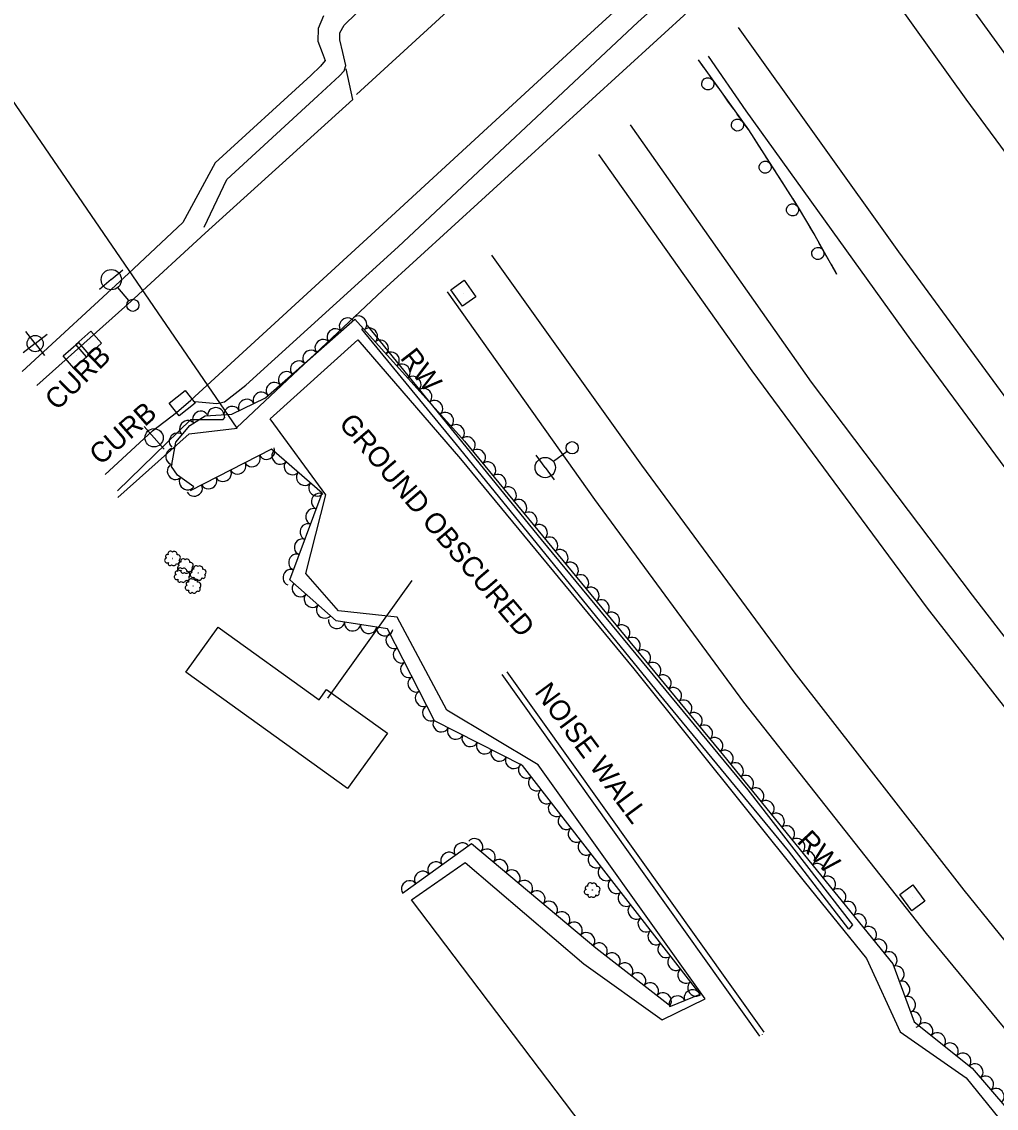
# Model space of a CAD drawing. Extents: x 1722896 to 1754269, y 648279 to 666297.
# Drawn here: x 1731974.7 to 1732214.8, y 650380.2 to 650647.8 of the extents above; entities that cross this region are included whole.
import ezdxf

# ---------------------------------------------------------------- set-up
doc = ezdxf.new("R2010")
doc.units = 0
for name, color, linetype in [('DESIGN - CENTERLINE - Proposed', 7, 'Continuous'), ('DESIGN - CENTERLINE - Proposed Text', 7, 'Continuous'), ('DESIGN - CONTOURS - Intermediate with optional Text', 7, 'Continuous'), ('DESIGN - SCRATCH - User 1', 7, 'Continuous'), ('SURVEY - CENTERLINE - Preliminary', 7, 'Continuous'), ('SURVEY - CENTERLINE - Preliminary Text', 7, 'Continuous'), ('SURVEY - DRAINAGE - Natural Features', 7, 'Continuous'), ('SURVEY - DTM - Breaklines', 7, 'Continuous'), ('SURVEY - VEGETATION - Features with Text', 7, 'Continuous')]:
    doc.layers.add(name, color=color, linetype=linetype)

msp = doc.modelspace()

# ---------------------------------------------------------------- linework, layer by layer
at = {"layer": 'DESIGN - CENTERLINE - Proposed'}
for points in [[(1732027.76, 650547.7), (1731948.68, 650663.25), (1732016.79, 650725.98), (1732087.03, 650790.21), (1732126.29, 650827.23)], [(1732204.27, 650710.7), (1732204.36, 650710.57), (1732139.74, 650651.07), (1732063.58, 650581.67), (1732027.75, 650547.92)]]:
    msp.add_lwpolyline(points, dxfattribs=at)
at = {"layer": 'DESIGN - CENTERLINE - Proposed Text'}
for points in [[(1731998.43, 650530.69), (1732015.98, 650546.35), (1732027.76, 650547.7)], [(1731998.43, 650530.69), (1732015.98, 650546.35), (1732027.76, 650547.7)], [(1732050.11, 650481.21), (1732070.87, 650510.2)], [(1732050.11, 650481.21), (1732070.87, 650510.2)]]:
    msp.add_lwpolyline(points, dxfattribs=at)
msp.add_lwpolyline([(1732015.16, 650487.66), (1732023.12, 650498.71), (1732047.97, 650480.81), (1732049.83, 650483.39), (1732064.8, 650472.61), (1732054.98, 650458.98)], close=True, dxfattribs=at)
at = {"layer": 'DESIGN - CONTOURS - Intermediate with optional Text'}
for q in [(1731975.77, 650571.55), (1731981.02, 650570.85), (1731975.07, 650566.29), (1731980.32, 650565.59)]:
    msp.add_line((1731978.04, 650568.57), q, dxfattribs=at)
msp.add_circle((1731978.04, 650568.57), 2, dxfattribs=at)
at = {"layer": 'DESIGN - SCRATCH - User 1'}
for points in [[(1732141.32, 650638.47), (1732153.75, 650621.19), (1732166.02, 650602.07), (1732170.07, 650595.18), (1732175.47, 650585.65)], [(1732141.32, 650638.47), (1732142.69, 650636.56)], [(1732143.62, 650635.26), (1732146.31, 650631.53)], [(1732147.24, 650630.23), (1732148.62, 650628.32)], [(1732148.62, 650628.32), (1732149.99, 650626.41)], [(1732150.92, 650625.11), (1732153.61, 650621.38)], [(1732154.48, 650620.04), (1732155.75, 650618.06)], [(1732155.75, 650618.06), (1732157.02, 650616.08)], [(1732157.89, 650614.74), (1732160.37, 650610.87)], [(1732161.24, 650609.52), (1732162.51, 650607.54)], [(1732162.51, 650607.54), (1732163.78, 650605.57)], [(1732164.64, 650604.22), (1732166.02, 650602.07), (1732167.05, 650600.31)], [(1732167.86, 650598.93), (1732169.05, 650596.9)], [(1732169.05, 650596.9), (1732170.07, 650595.18), (1732170.24, 650594.87)], [(1732171.03, 650593.48), (1732173.3, 650589.48)], [(1732174.09, 650588.09), (1732175.25, 650586.04)], [(1732175.25, 650586.04), (1732175.47, 650585.65)], [(1732059.81, 650573.02), (1732102.66, 650520.33), (1732153.61, 650458.61), (1732179.34, 650425.38), (1732178.44, 650424.33), (1732163.6, 650443.58), (1732131.75, 650482.28), (1732081.81, 650543.7), (1732058.48, 650572.12), (1732058.68, 650572.25)], [(1732059.56, 650572.85), (1732059.81, 650573.02)], [(1732156.53, 650397.99), (1732124.59, 650442.81), (1732093.08, 650487.08)], [(1732094.24, 650487.73), (1732157.49, 650398.95)], [(1732157.16, 650398.34), (1732157.11, 650398.29)]]:
    msp.add_lwpolyline(points, dxfattribs=at)
for centre, start, end in [((1732143.74, 650632.54), 148.9899, 148.9801), ((1732151.04, 650622.39), 148.9899, 148.9801), ((1732157.86, 650612.01), 145.9594, 145.9496), ((1732164.61, 650601.49), 145.9594, 145.9496), ((1732170.85, 650590.76), 142.8362, 142.8264)]:
    msp.add_arc(centre, 1.5, start, end, dxfattribs=at)
at = {"layer": 'SURVEY - CENTERLINE - Preliminary'}
msp.add_lwpolyline([(1732127.41, 650356.71), (1732070.78, 650431.51), (1732083.93, 650440.75), (1732113.2, 650415.77), (1732132.47, 650401.96), (1732143.05, 650407.14), (1732101.92, 650464.8), (1732079.44, 650478.24), (1732067.24, 650501.17), (1732052.76, 650502.71), (1732044.68, 650511.92), (1732049.65, 650531.34), (1732035.93, 650550.04), (1732057.56, 650569.48), (1732082.82, 650540.17), (1732125.54, 650488.48), (1732167.48, 650436.04), (1732182.81, 650417.11), (1732191.08, 650399.01), (1732207.4, 650387.66), (1732234.27, 650354.45)], dxfattribs=at)
at = {"layer": 'SURVEY - CENTERLINE - Preliminary Text'}
for points in [[(1732017.39, 650554.27), (1732022.82, 650553.77), (1732024.65, 650554.19), (1732029.89, 650558.35), (1732067.45, 650592.39), (1732126.48, 650647.73), (1732181.2, 650696.92), (1732205.98, 650719.16), (1732222.53, 650735.2), (1732218.17, 650739.56), (1732238.67, 650758.11), (1732258.13, 650774.82)], [(1732019.7, 650597.23), (1732025.25, 650609), (1732047.69, 650629.57), (1732053, 650634.51), (1732054.14, 650635.79), (1732054.58, 650637.05), (1732053.81, 650640.28), (1732053.05, 650643.35), (1732053.09, 650645.15), (1732054.13, 650647), (1732057.12, 650649.84), (1732093.89, 650683.21), (1732153.25, 650737.93), (1732155.46, 650738.31), (1732157.6, 650737.83), (1732164.05, 650736.16), (1732178.68, 650749.33)], [(1732170.07, 650733.54), (1732117.51, 650685.24), (1732057.17, 650629.93)], [(1732207.17, 650729.36), (1732164.78, 650690.72), (1732112.04, 650642.46), (1732063.76, 650598.07), (1732016.4, 650554.62)], [(1732656.46, 650208.97), (1732630.79, 650210.68), (1732597.44, 650234.52), (1732563.92, 650259.85), (1732539.06, 650279.24), (1732510.61, 650303.52), (1732476.55, 650333.08), (1732451.2, 650357.5), (1732426.04, 650382.28), (1732392, 650419.06), (1732364.07, 650450.35), (1732335.07, 650484.5), (1732308.14, 650518.04), (1732281.58, 650551.51), (1732254.43, 650588.37), (1732226.27, 650627.09), (1732196.58, 650668.11), (1732187.42, 650681.36)], [(1732177.23, 650670.78), (1732207.28, 650628.76), (1732240.27, 650584.01), (1732277.17, 650534.26), (1732308.17, 650494.8), (1732347.59, 650447.31), (1732385.2, 650405.27), (1732423.32, 650365.2), (1732455.21, 650333.82), (1732493.46, 650299.04), (1732525.54, 650271.93), (1732567.3, 650239.43), (1732600.18, 650214.95), (1732636.27, 650190.54), (1732676.54, 650164.63), (1732716.69, 650140.93), (1732760.83, 650117.07), (1732799.05, 650097.55)], [(1732049.03, 650649.33), (1732047.73, 650646.22), (1732047.69, 650643.08), (1732048.73, 650640.25), (1732049.45, 650638.28), (1732048.33, 650636.86), (1732045.97, 650634.61), (1732022.36, 650613.05), (1732014.38, 650598.43), (1732001.02, 650585.83), (1731974.85, 650561.69)], [(1732778.62, 650068.08), (1732748.36, 650083.69), (1732696.91, 650111.79), (1732659.43, 650133.9), (1732618.71, 650159.74), (1732569.4, 650193.82), (1732523.94, 650227.88), (1732487.08, 650258.27), (1732439.71, 650299.95), (1732393.89, 650344.9), (1732345.63, 650396.27), (1732315.87, 650430.1), (1732281.7, 650470.92), (1732248.95, 650512.82), (1732219.45, 650552.09), (1732190.79, 650591.17), (1732151.27, 650646.44)], [(1732143.79, 650639.34), (1732153.13, 650625.88), (1732193.64, 650569.45), (1732232.08, 650517.33), (1732271.5, 650466.99), (1732311.93, 650418.7), (1732362.13, 650362.86), (1732398.54, 650325.18), (1732431.93, 650292.77), (1732461.34, 650265.94), (1732489.99, 650242.08), (1732529.79, 650210.06), (1732579.85, 650173.43), (1732625.15, 650142.57), (1732670.82, 650114.68), (1732714.02, 650089.97), (1732772.83, 650059.19)], [(1732019.92, 650595.73), (1732056.26, 650628.73), (1732054.68, 650636.23)], [(1732758.57, 650037.66), (1732711.61, 650061.49), (1732673.88, 650082.51), (1732628.45, 650110.48), (1732577.41, 650143.72), (1732530.35, 650177.49), (1732484.46, 650213.66), (1732441.73, 650249.76), (1732398.13, 650290.47), (1732360.12, 650328.45), (1732319.14, 650371.25), (1732281.23, 650415.01), (1732242.63, 650463.01), (1732208.97, 650506.59), (1732169.3, 650559.09), (1732132.45, 650611.35), (1732124.72, 650622.47)], [(1732116.77, 650615.12), (1732154.56, 650561.87), (1732197.78, 650503.43), (1732240.48, 650448.7), (1732279.53, 650400.92), (1732304.66, 650372.14), (1732330.13, 650344.56), (1732363.24, 650310.31), (1732395.54, 650278.52), (1732428.24, 650247.68), (1732459.96, 650219.74), (1732492.98, 650192.82), (1732520.72, 650171.8), (1732555.83, 650146.42), (1732590.52, 650122.88), (1732625.42, 650100.02), (1732661.59, 650078.24), (1732702.96, 650054.7), (1732752.88, 650028.99)], [(1731978.43, 650558.21), (1732002.46, 650579.65), (1732019.92, 650595.73)], [(1732733.54, 649998.91), (1732697.9, 650017.32), (1732664.31, 650035.65), (1732632.41, 650053.89), (1732595.91, 650076.67), (1732547.12, 650109.2), (1732508.27, 650137.06), (1732471.36, 650165.08), (1732438.09, 650192.32), (1732405.65, 650220.47), (1732374.22, 650249.28), (1732344.15, 650278.5), (1732307.7, 650316.31), (1732271.64, 650356.22), (1732236.11, 650397.76), (1732206.87, 650433.94), (1732165.04, 650487.7), (1732127.45, 650538.61), (1732090.56, 650590.36)], [(1732079.49, 650581.32), (1732115.82, 650530.17), (1732152.56, 650480.2), (1732197.55, 650423.24), (1732252.84, 650356.13), (1732285.21, 650320.71), (1732328.53, 650274.62), (1732371.38, 650233.06), (1732418.71, 650190.71), (1732459.87, 650156.35), (1732498.95, 650126.41), (1732536.17, 650100.02), (1732559.49, 650083.88), (1732563.6, 650063.54)], [(1731995.28, 650536.28), (1732006.93, 650547.11), (1732012.84, 650551.61), (1732016.4, 650554.62)], [(1731998.32, 650532.27), (1732016.42, 650549.84), (1732024.31, 650549.83), (1732024.75, 650550.34)]]:
    msp.add_lwpolyline(points, dxfattribs=at)
at = {"layer": 'SURVEY - DRAINAGE - Natural Features'}
for p, q in [((1732083.5, 650580.97), (1732083.5, 650580.97)), ((1731991.22, 650568.49), (1731991.22, 650568.49)), ((1731988.14, 650565.68), (1731988.14, 650565.68)), ((1732014.24, 650553.89), (1732014.24, 650553.89)), ((1732194.13, 650432), (1732194.13, 650432))]:
    msp.add_line(p, q, dxfattribs=at)
for points in [[(1732080.42, 650581.84), (1732083.68, 650584.16), (1732086.58, 650580.09), (1732083.32, 650577.77), (1732080.42, 650581.84)], [(1731991.78, 650571.64), (1731994.41, 650568.63), (1731990.65, 650565.33), (1731988.02, 650568.34), (1731991.78, 650571.64)], [(1731988.7, 650568.83), (1731991.34, 650565.83), (1731987.59, 650562.53), (1731984.95, 650565.53), (1731988.7, 650568.83)], [(1732014.96, 650557.01), (1732017.44, 650553.88), (1732013.52, 650550.77), (1732011.04, 650553.9), (1732014.96, 650557.01)], [(1732191.04, 650432.83), (1732194.26, 650435.2), (1732197.23, 650431.18), (1732194.01, 650428.81), (1732191.04, 650432.83)]]:
    msp.add_lwpolyline(points, dxfattribs=at)
at = {"layer": 'SURVEY - DTM - Breaklines'}
for p, q in [((1731996.79, 650584.31), (1731999.65, 650586.73)), ((1731996.79, 650584.31), (1731993.92, 650581.88)), ((1732001.15, 650579.15), (1731998.4, 650582.4)), ((1732007.33, 650545.36), (1732004.86, 650548.18)), ((1732007.33, 650545.36), (1732009.81, 650542.54)), ((1732103.69, 650538.02), (1732101.47, 650541.04)), ((1732109.12, 650542.02), (1732105.7, 650539.5)), ((1732103.69, 650538.02), (1732105.91, 650535))]:
    msp.add_line(p, q, dxfattribs=at)
for centre, radius in [((1731996.79, 650584.31), 2.5), ((1732002.11, 650578), 1.5), ((1732007.33, 650545.36), 2.25), ((1732110.33, 650542.91), 1.5), ((1732103.69, 650538.02), 2.5)]:
    msp.add_circle(centre, radius, dxfattribs=at)
at = {"layer": 'SURVEY - VEGETATION - Features with Text'}
for points in [[(1732017.11, 650533.3), (1732013.11, 650536.13), (1732011.66, 650538.29), (1732012.68, 650544.24), (1732016.15, 650548.38), (1732019.9, 650550.74), (1732026.5, 650551.18), (1732034.78, 650555.23), (1732056.75, 650574.57), (1732083.8, 650544.52), (1732147.57, 650467.07), (1732189.29, 650415.74), (1732194.58, 650401.45), (1732208.88, 650390.07), (1732234.44, 650360.27)], [(1732068.56, 650433.16), (1732085.55, 650445.39), (1732116.11, 650419.72), (1732134.59, 650405.31), (1732141.86, 650408.31), (1732098.07, 650464.66), (1732076.37, 650475.63), (1732064.86, 650498.32), (1732052.16, 650500.28), (1732040.74, 650510.37), (1732048.75, 650531.75), (1732036.24, 650542.54), (1732016.21, 650532.32)]]:
    msp.add_lwpolyline(points, dxfattribs=at)
for centre in [(1732011.9, 650515.63), (1732015.05, 650513.75), (1732014.26, 650511.52), (1732018.21, 650512.05), (1732016.96, 650508.85), (1732115.27, 650433.95)]:
    msp.add_circle(centre, 0.022, dxfattribs=at)
for centre, radius, start, end in [((1732010.56, 650515.18), 0.629, 104.5685, 297.9882), ((1732010.59, 650516.17), 0.433, 64.5478, 243.2934), ((1732011.38, 650516.77), 0.631, 42.4316, 199.2206), ((1732012.29, 650516.64), 0.719, 351.4844, 129.0086), ((1732013.11, 650515.83), 0.714, 302.3802, 98.2187), ((1732011.26, 650514.36), 0.479, 147.1871, 324.5063), ((1732012.15, 650514.54), 0.679, 222.4742, 349.3199), ((1732013.13, 650514.84), 0.527, 232.6331, 47.6334), ((1732013.7, 650513.3), 0.629, 104.5685, 297.9882), ((1732013.73, 650512.66), 0.631, 42.4316, 199.2206), ((1732013.74, 650514.3), 0.433, 64.5478, 243.2934), ((1732014.52, 650514.9), 0.631, 42.4316, 199.2206), ((1732014.65, 650512.53), 0.719, 351.4844, 129.0086), ((1732015.44, 650514.76), 0.719, 351.4844, 129.0086), ((1732016.28, 650512.96), 0.527, 232.6331, 47.6334), ((1732016.25, 650513.95), 0.714, 302.3802, 98.2187), ((1732016.91, 650512.59), 0.433, 64.5478, 243.2934), ((1732017.69, 650513.19), 0.631, 42.4316, 199.2206), ((1732018.61, 650513.06), 0.719, 351.4844, 129.0086), ((1732019.42, 650512.25), 0.714, 302.3802, 98.2187), ((1732012.91, 650511.07), 0.629, 104.5685, 297.9882), ((1732012.95, 650512.06), 0.433, 64.5478, 243.2934), ((1732013.61, 650510.25), 0.479, 147.1871, 324.5063), ((1732014.4, 650512.49), 0.479, 147.1871, 324.5063), ((1732014.5, 650510.43), 0.679, 222.4742, 349.3199), ((1732015.29, 650512.67), 0.679, 222.4742, 349.3199), ((1732015.49, 650510.73), 0.527, 232.6331, 47.6334), ((1732015.46, 650511.72), 0.714, 302.3802, 98.2187), ((1732016.43, 650510), 0.631, 42.4316, 199.2206), ((1732016.87, 650511.6), 0.629, 104.5685, 297.9882), ((1732017.35, 650509.87), 0.719, 351.4844, 129.0086), ((1732017.57, 650510.78), 0.479, 147.1871, 324.5063), ((1732018.46, 650510.96), 0.679, 222.4742, 349.3199), ((1732019.45, 650511.26), 0.527, 232.6331, 47.6334), ((1732015.62, 650508.41), 0.629, 104.5685, 297.9882), ((1732015.65, 650509.4), 0.433, 64.5478, 243.2934), ((1732016.31, 650507.59), 0.479, 147.1871, 324.5063), ((1732017.2, 650507.77), 0.679, 222.4742, 349.3199), ((1732018.19, 650508.06), 0.527, 232.6331, 47.6334), ((1732018.16, 650509.06), 0.714, 302.3802, 98.2187), ((1732114.75, 650435.09), 0.631, 42.4316, 199.2206), ((1732115.66, 650434.96), 0.719, 351.4844, 129.0086), ((1732113.93, 650433.5), 0.629, 104.5685, 297.9882), ((1732113.96, 650434.5), 0.433, 64.5478, 243.2934), ((1732114.63, 650432.68), 0.479, 147.1871, 324.5063), ((1732115.52, 650432.86), 0.679, 222.4742, 349.3199), ((1732116.5, 650433.16), 0.527, 232.6331, 47.6334), ((1732116.48, 650434.15), 0.714, 302.3802, 98.2187)]:
    msp.add_arc(centre, radius, start, end, dxfattribs=at)
for centre, major_axis in [((1732054.89, 650572.94), (1.5, 1.32)), ((1732057.77, 650573.43), (1.34, -1.49)), ((1732051.89, 650570.29), (1.5, 1.32)), ((1732060.45, 650570.46), (1.34, -1.49)), ((1732048.89, 650567.65), (1.5, 1.32)), ((1732063.12, 650567.49), (1.34, -1.49)), ((1732045.89, 650565.01), (1.5, 1.32)), ((1732065.8, 650564.51), (1.34, -1.49)), ((1732042.88, 650562.36), (1.5, 1.32)), ((1732039.88, 650559.72), (1.5, 1.32)), ((1732068.48, 650561.54), (1.34, -1.49)), ((1732036.88, 650557.08), (1.5, 1.32)), ((1732071.15, 650558.57), (1.34, -1.49)), ((1732033.7, 650554.7), (1.8, 0.88)), ((1732073.83, 650555.59), (1.34, -1.49)), ((1732026.51, 650551.19), (1.8, 0.88)), ((1732030.1, 650552.94), (1.8, 0.88)), ((1732076.5, 650552.62), (1.34, -1.49)), ((1732018.74, 650550.01), (1.69, 1.06)), ((1732022.52, 650550.91), (2, 0.13)), ((1732079.18, 650549.65), (1.34, -1.49)), ((1732015.54, 650547.66), (1.28, 1.53)), ((1732081.86, 650546.67), (1.34, -1.49)), ((1732012.97, 650544.6), (1.28, 1.53)), ((1732084.5, 650543.67), (1.27, -1.54)), ((1732012.08, 650540.75), (0.33, 1.97)), ((1732035.09, 650541.95), (-1.78, -0.91)), ((1732087.04, 650540.58), (1.27, -1.54)), ((1732031.53, 650540.13), (-1.78, -0.91)), ((1732038.29, 650540.77), (-1.51, 1.31)), ((1732089.58, 650537.49), (1.27, -1.54)), ((1732012.5, 650537.04), (-1.12, 1.66)), ((1732024.4, 650536.5), (-1.78, -0.91)), ((1732027.96, 650538.32), (-1.78, -0.91)), ((1732041.32, 650538.16), (-1.51, 1.31)), ((1732015.48, 650534.45), (-1.63, 1.16)), ((1732020.84, 650534.68), (-1.78, -0.91)), ((1732044.35, 650535.54), (-1.51, 1.31)), ((1732092.12, 650534.41), (1.27, -1.54)), ((1732017.27, 650532.86), (-1.78, -0.91)), ((1732047.38, 650532.93), (-1.51, 1.31)), ((1732047.98, 650529.7), (0.7, 1.87)), ((1732094.67, 650531.32), (1.27, -1.54)), ((1732097.21, 650528.23), (1.27, -1.54)), ((1732046.58, 650525.95), (0.7, 1.87)), ((1732099.75, 650525.14), (1.27, -1.54)), ((1732045.18, 650522.21), (0.7, 1.87)), ((1732102.29, 650522.05), (1.27, -1.54)), ((1732104.84, 650518.97), (1.27, -1.54)), ((1732043.77, 650518.46), (0.7, 1.87)), ((1732042.37, 650514.72), (0.7, 1.87)), ((1732107.38, 650515.88), (1.27, -1.54)), ((1732040.97, 650510.97), (0.7, 1.87)), ((1732109.92, 650512.79), (1.27, -1.54)), ((1732112.46, 650509.7), (1.27, -1.54)), ((1732043.26, 650508.15), (-1.5, 1.32)), ((1732115.01, 650506.62), (1.27, -1.54)), ((1732046.25, 650505.5), (-1.5, 1.32)), ((1732117.55, 650503.53), (1.27, -1.54)), ((1732049.25, 650502.85), (-1.5, 1.32)), ((1732120.09, 650500.44), (1.27, -1.54)), ((1732052.28, 650500.26), (-1.98, 0.3)), ((1732056.23, 650499.65), (-1.98, 0.3)), ((1732122.63, 650497.35), (1.27, -1.54)), ((1732060.19, 650499.04), (-1.98, 0.3)), ((1732064.14, 650498.43), (-1.98, 0.3)), ((1732066.34, 650495.41), (-0.9, 1.78)), ((1732125.18, 650494.26), (1.27, -1.54)), ((1732068.15, 650491.84), (-0.9, 1.78)), ((1732127.72, 650491.18), (1.27, -1.54)), ((1732069.96, 650488.27), (-0.9, 1.78)), ((1732130.26, 650488.09), (1.27, -1.54)), ((1732071.77, 650484.7), (-0.9, 1.78)), ((1732132.8, 650485), (1.27, -1.54)), ((1732135.35, 650481.91), (1.27, -1.54)), ((1732073.58, 650481.14), (-0.9, 1.78)), ((1732137.89, 650478.82), (1.27, -1.54)), ((1732075.38, 650477.57), (-0.9, 1.78)), ((1732078, 650474.8), (-1.79, 0.9)), ((1732140.43, 650475.74), (1.27, -1.54)), ((1732081.57, 650473), (-1.79, 0.9)), ((1732142.97, 650472.65), (1.27, -1.54)), ((1732085.14, 650471.2), (-1.79, 0.9)), ((1732088.71, 650469.39), (-1.79, 0.9)), ((1732145.52, 650469.56), (1.27, -1.54)), ((1732092.28, 650467.59), (-1.79, 0.9)), ((1732148.06, 650466.47), (1.26, -1.55)), ((1732095.85, 650465.79), (-1.79, 0.9)), ((1732099, 650463.47), (-1.23, 1.58)), ((1732150.58, 650463.37), (1.26, -1.55)), ((1732153.1, 650460.26), (1.26, -1.55)), ((1732101.45, 650460.31), (-1.23, 1.58)), ((1732103.9, 650457.15), (-1.23, 1.58)), ((1732155.63, 650457.16), (1.26, -1.55)), ((1732106.36, 650453.99), (-1.23, 1.58)), ((1732158.15, 650454.05), (1.26, -1.55)), ((1732108.81, 650450.84), (-1.23, 1.58)), ((1732160.67, 650450.95), (1.26, -1.55)), ((1732111.27, 650447.68), (-1.23, 1.58)), ((1732163.19, 650447.85), (1.26, -1.55)), ((1732086.37, 650444.7), (1.53, -1.29)), ((1732113.72, 650444.52), (-1.23, 1.58)), ((1732165.72, 650444.74), (1.26, -1.55)), ((1732079.93, 650441.34), (1.62, 1.17)), ((1732083.17, 650443.67), (1.62, 1.17)), ((1732089.43, 650442.13), (1.53, -1.29)), ((1732168.24, 650441.64), (1.26, -1.55)), ((1732076.68, 650439), (1.62, 1.17)), ((1732092.5, 650439.55), (1.53, -1.29)), ((1732116.18, 650441.36), (-1.23, 1.58)), ((1732170.76, 650438.53), (1.26, -1.55)), ((1732073.43, 650436.66), (1.62, 1.17)), ((1732095.56, 650436.98), (1.53, -1.29)), ((1732118.63, 650438.2), (-1.23, 1.58)), ((1732070.19, 650434.33), (1.62, 1.17)), ((1732098.62, 650434.41), (1.53, -1.29)), ((1732121.08, 650435.04), (-1.23, 1.58)), ((1732173.29, 650435.43), (1.26, -1.55)), ((1732101.69, 650431.84), (1.53, -1.29)), ((1732123.54, 650431.88), (-1.23, 1.58)), ((1732175.81, 650432.33), (1.26, -1.55)), ((1732104.75, 650429.26), (1.53, -1.29)), ((1732125.99, 650428.73), (-1.23, 1.58)), ((1732178.33, 650429.22), (1.26, -1.55)), ((1732107.81, 650426.69), (1.53, -1.29)), ((1732180.86, 650426.12), (1.26, -1.55)), ((1732110.88, 650424.12), (1.53, -1.29)), ((1732128.45, 650425.57), (-1.23, 1.58)), ((1732183.38, 650423.01), (1.26, -1.55)), ((1732113.94, 650421.55), (1.53, -1.29)), ((1732130.9, 650422.41), (-1.23, 1.58)), ((1732185.9, 650419.91), (1.26, -1.55)), ((1732117.03, 650419.01), (1.58, -1.23)), ((1732133.36, 650419.25), (-1.23, 1.58)), ((1732120.18, 650416.55), (1.58, -1.23)), ((1732135.81, 650416.09), (-1.23, 1.58)), ((1732188.42, 650416.81), (1.26, -1.55)), ((1732123.34, 650414.09), (1.58, -1.23)), ((1732138.26, 650412.93), (-1.23, 1.58)), ((1732190.2, 650413.28), (0.69, -1.88)), ((1732126.49, 650411.63), (1.58, -1.23)), ((1732129.64, 650409.17), (1.58, -1.23)), ((1732140.72, 650409.77), (-1.23, 1.58)), ((1732191.59, 650409.53), (0.69, -1.88)), ((1732132.8, 650406.71), (1.58, -1.23)), ((1732139.88, 650407.49), (1.85, 0.76)), ((1732136.19, 650405.97), (1.85, 0.76)), ((1732192.98, 650405.77), (0.69, -1.88)), ((1732194.37, 650402.02), (0.69, -1.88)), ((1732197.23, 650399.34), (1.56, -1.25)), ((1732200.36, 650396.85), (1.56, -1.25)), ((1732203.49, 650394.36), (1.56, -1.25)), ((1732206.62, 650391.87), (1.56, -1.25)), ((1732209.61, 650389.22), (1.3, -1.52)), ((1732212.21, 650386.19), (1.3, -1.52)), ((1732214.81, 650383.15), (1.3, -1.52))]:
    msp.add_ellipse(centre, major_axis=major_axis, ratio=0.940188, start_param=0, end_param=3.141593, dxfattribs=at)

# ---------------------------------------------------------------- texts
at = {"layer": 'DESIGN - SCRATCH - User 1'}
for s, rotation, p in [('CURB', 43.934, (1731983.38, 650551.88)), ('RW', 307.7085, (1732067.76, 650564.99)), ('CURB', 41.1003, (1731994.11, 650538.41)), ('NOISE WALL', 306.4944, (1732100.89, 650482.72)), ('RW', 313.2105, (1732165.45, 650445.78))]:
    msp.add_text(s, height=5, rotation=rotation, dxfattribs=at).set_placement(p)
at = {"layer": 'SURVEY - CENTERLINE - Preliminary'}
msp.add_text('GROUND OBSCURED', height=5, rotation=310.4491, dxfattribs=at).set_placement((1732052.62, 650548.69))

doc.saveas('drawing.dxf')
